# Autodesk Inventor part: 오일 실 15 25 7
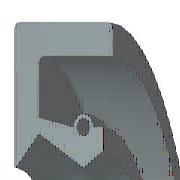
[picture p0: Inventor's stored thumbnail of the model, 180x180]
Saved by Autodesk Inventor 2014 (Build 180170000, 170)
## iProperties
Created: 2012-02
Part Number: 오일 실 15 25 7
Material: 고무
Description: 오일-실
Document SubType Name: Modeling
Standard: KS B 2804
Designer: mduedu
Standards Organization: KS
Language: ko-KR
Size Designation: D - 15 25 7
Categories: <MemberInstance><Categories><Category DisplayName="샤프트 부품" InternalName="7f7aeb1f-a693-4053-b835-cee3144e0d98" Mnemonic="SHFT"><Category DisplayName="실링" Intern
Density: 0.93 g/cm^3
Mass: 1.46464 g
Surface Area: 21.6685 cm^2
Volume: 1.57488 cm^3
Appearance: 고무 - 검은색 - 버전 1.1
IsCustomPart: 1
Author: mduedu
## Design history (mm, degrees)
revolve "본체" stored, may be unused: angle "d17" = 90 deg
revolve "스프링1" stored, may be unused: angle "d18" = 90 deg
body "Solid1"
sketch "스케치1"
  geometry: L1 (0, 12.5)-(7, 12.5); L2 (7, 10.75)-(1.75, 10.75); L3 (1.75, 9.25)-(4.9, 7.5); L4 (4.9, 7.5)-(0, 7.5); L5 (0, 0)-(9.586, 0) reference; L6 (4.9, 7.5)-(6.3, 8.375); L7 (0, 18)-(0, -3) reference; L8 (-1.941, 0)-(11.507, 0) reference; L9 (4.2, 9.6)-(1.75, 10.09); L10 (1.75, 10.09)-(1.75, 10.75); L11 (0, 12.5)-(0, 7.588); L12 (4.9, 7.5)-(0, 7.5); L13 (1.75, 9.25)-(0.152, 7.528); L14 (7, 12.5)-(7, 10.75); L15 (5.6, 9.6)-(6.3, 9.6); L16 (6.3, 9.6)-(6.3, 8.375); C1 r 0.455 at (4.9, 9.6); A1 r 0.7 centre (4.9, 9.6) between (5.6, 9.6) and (4.2, 9.6); A2 r 0.088 centre (0.088, 7.588) between (0, 7.588) and (0.152, 7.528); 1 further point
  constraints: 28 end point, 5 horizontal alignment, 5 point on line, 4 point on circle, 4 vertical alignment, 3 centre point, 3 tangent, 2 collinear, 2 horizontal, 2 perpendicular, 1 coincident, 1 parallel
  dimensions: "d0" = 25 diameter of L1 L5 (= SD2); "d1" = 1.75 distance of L1.end L2.start (= SD); "d2" = 0.91 diameter of C1 (= SPDI); "d3" = 1.4 diameter of A1 (= SPDA); "d4" = 15 diameter of L3.end L5 (= NND); "d5" = 18.5 diameter of L3.start L5 (= TKDM); "d7" = 20.18 diameter of L9.end L5 (= TKDM + 0.24 x SWDT); "d8" = 1.75 distance between parallel lines of L11 L10 (= SD); "d9" = 4.9 distance from line of L11 C1.centre (= SPDST); "d10" = 19.2 diameter of C1.centre L5 (= HLDM); "d11" = 0.0875 radius of A2 (= 0.25 x LAB); "d12" = 6.3 distance between parallel lines of L11 L16 (= SDI); "d13" = 16.75 diameter of L6.end L5 (= ABDM); "d14" = 7 distance from line of L11 L1.end (= SWDT)
fillet "모깎기1" dims "d6" = 0.3 (= RR)
other parameters: "SD2" = 25 [user parameter; used in 1 equation term], "SWDT" = 7 [user parameter; used in 2 equation terms], "RR" = 0.3 [user parameter; used in 1 equation term], "SD" = 1.75 [user parameter; used in 2 equation terms], "NND" = 15 [user parameter; used in 1 equation term], "SPDA" = 1.4 [user parameter; used in 1 equation term], "SPDI" = 0.91 [user parameter; used in 1 equation term], "TKDM" = 18.5 [user parameter; used in 2 equation terms], "HLDM" = 19.2 [user parameter; used in 1 equation term], "ABDM" = 16.75 [user parameter; used in 1 equation term], "SDI" = 6.3 [user parameter; used in 1 equation term], "SPDST" = 4.9 [user parameter; used in 1 equation term], "LAB" = 0.35 [user parameter; used in 1 equation term], "d15" = 0, "d16" = 0, "d19" = 0
